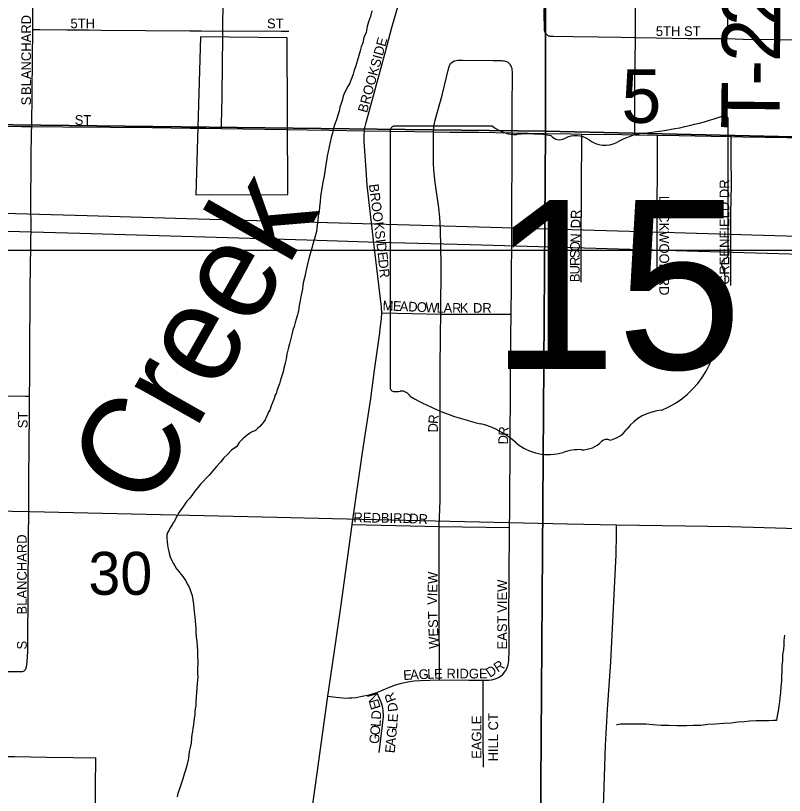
# Model space of a CAD drawing. Extents: x 0 to 68, y 0 to 52.9.
# Drawn here: x 44.415 to 45.206, y 36.702 to 37.505 of the extents above; entities that cross this region are included whole.
import ezdxf

# ---------------------------------------------------------------- set-up
doc = ezdxf.new("R2010")
doc.units = 0
for name, color, linetype in [('Default', 7, 'Continuous'), ('GM_X_County_Road', 7, 'Continuous'), ('GM_X_Minor_Lake', 7, 'Continuous'), ('GM_X_Minor_River', 7, 'Continuous'), ('GM_X_Minor_River_Text', 7, 'Continuous'), ('GM_X_State_Route', 7, 'Continuous'), ('GM_X_State_Shield', 7, 'Continuous'), ('GM_X_Township_Road', 7, 'Continuous'), ('GM_X_Township_Road_Text', 7, 'Continuous'), ('GM_X_Township_Subdivision', 7, 'Continuous'), ('GM_X_Township_Subdivision_Text', 7, 'Continuous')]:
    doc.layers.add(name, color=color, linetype=linetype)

msp = doc.modelspace()

# ---------------------------------------------------------------- linework, layer by layer
at = {"layer": 'Default'}
msp.add_line((41.10506, 37.2633), (50.34506, 37.2633), dxfattribs=at)
for points in [[(43.93627, 38.46518), (44.96064, 38.44451), (44.96032, 37.38586), (43.92065, 37.39833), (43.9204, 37.41034)], [(44.96064, 38.44451), (46.03674, 38.4191), (46.02513, 37.36139), (44.96032, 37.38586)], [(44.96032, 37.38586), (44.95281, 36.32851), (43.90273, 36.34073), (43.92065, 37.39833)], [(44.96032, 37.38586), (46.02513, 37.36139), (46.0139, 36.30128), (44.95281, 36.32851)]]:
    msp.add_lwpolyline(points, close=True, dxfattribs=at)
for points in [[(44.43227, 37.4907), (44.43277, 37.54226), (44.43273, 37.56524), (44.43292, 37.58162), (44.43311, 37.58761)], [(45.0529, 37.48225), (45.0529, 37.49022), (45.05337, 37.55402), (45.05339, 37.57852)], [(45.14747, 37.48118), (45.1476, 37.48856), (45.14788, 37.4984), (45.14842, 37.57791)], [(44.62788, 37.48889), (44.62836, 37.52296), (44.62854, 37.54361), (44.62857, 37.54875), (44.62898, 37.56606)], [(44.7737, 37.38631), (44.77418, 37.38918), (44.77571, 37.39488), (44.79524, 37.46651), (44.8022, 37.49277), (44.81318, 37.53091)], [(44.95931, 37.529), (44.9587, 37.50654), (44.95878, 37.49245), (44.95877, 37.49083), (44.95889, 37.48984), (44.95914, 37.48902), (44.95947, 37.48814), (44.95997, 37.48724), (44.96055, 37.4865), (44.96105, 37.48587), (44.96154, 37.48534), (44.96191, 37.48496), (44.96254, 37.48451), (44.96332, 37.48418), (44.96438, 37.48394), (44.96519, 37.48381), (44.96679, 37.48366), (44.96851, 37.48356), (44.98874, 37.48327), (45.01464, 37.48288), (45.03824, 37.48261), (45.0529, 37.48225)], [(44.43128, 37.39053), (44.43201, 37.46027), (44.43227, 37.4907)], [(44.43227, 37.4907), (44.43977, 37.49058), (44.46755, 37.49014), (44.48982, 37.49011), (44.50279, 37.49006), (44.59414, 37.48918), (44.60607, 37.48921), (44.62788, 37.48889)], [(44.62669, 37.38872), (44.62679, 37.39513), (44.62693, 37.40488), (44.62743, 37.42337), (44.62726, 37.42627), (44.62752, 37.43021), (44.62781, 37.44769), (44.62788, 37.48889)], [(44.62788, 37.48889), (44.67163, 37.48938), (44.68813, 37.4889), (44.69614, 37.48871)], [(45.05235, 37.38206), (45.05221, 37.43132), (45.0529, 37.48225)], [(45.0529, 37.48225), (45.07425, 37.48214), (45.10712, 37.48143), (45.14088, 37.48131), (45.14747, 37.48118)], [(45.14747, 37.48118), (45.16376, 37.48077), (45.19824, 37.48024), (45.21963, 37.47986), (45.22496, 37.47984)], [(44.84503, 37.38511), (44.84525, 37.38851), (44.84583, 37.39242), (44.84678, 37.39711), (44.85374, 37.42297), (44.86065, 37.45143), (44.86133, 37.45323), (44.86194, 37.45435), (44.86261, 37.45518), (44.86323, 37.4559)], [(44.92587, 37.38409), (44.92595, 37.41276), (44.92641, 37.4423), (44.92635, 37.44515), (44.92626, 37.44732), (44.92611, 37.44883), (44.92583, 37.45037), (44.9253, 37.45177), (44.92489, 37.45281), (44.92438, 37.45375), (44.924, 37.45447), (44.92337, 37.45522), (44.92255, 37.45604), (44.92195, 37.45647), (44.9214, 37.4569), (44.92042, 37.45741), (44.91933, 37.45774), (44.91825, 37.458), (44.91774, 37.45807), (44.91646, 37.45814), (44.91492, 37.45815), (44.90626, 37.45843), (44.87529, 37.45875), (44.86998, 37.45852), (44.86837, 37.45832), (44.86636, 37.45782), (44.86476, 37.45711), (44.86323, 37.4559)], [(44.37678, 37.39129), (44.42071, 37.39059), (44.43128, 37.39053)], [(44.42914, 37.11294), (44.42941, 37.13211), (44.42937, 37.15183), (44.42981, 37.22402), (44.43056, 37.28964), (44.43046, 37.30608), (44.43073, 37.35858), (44.43119, 37.3848), (44.43128, 37.39053)], [(44.43128, 37.39053), (44.46332, 37.39034), (44.51249, 37.38996), (44.55512, 37.38971), (44.59444, 37.38901), (44.61054, 37.389), (44.62669, 37.38872)], [(44.62669, 37.38872), (44.73757, 37.38674), (44.7737, 37.38631)], [(44.7737, 37.38631), (44.77331, 37.38154), (44.7734, 37.37522), (44.77516, 37.34613), (44.77639, 37.33038), (44.77923, 37.30625), (44.78351, 37.26792), (44.79105, 37.20461), (44.79154, 37.19887)], [(44.7737, 37.38631), (44.82588, 37.38538), (44.84503, 37.38511)], [(44.85258, 37.19723), (44.85294, 37.24938), (44.85234, 37.2841), (44.85155, 37.29719), (44.85049, 37.30696), (44.84676, 37.33293), (44.84537, 37.34596), (44.84507, 37.35251), (44.84482, 37.38104), (44.84503, 37.38511)], [(44.84503, 37.38511), (44.86194, 37.38488), (44.89145, 37.38473), (44.92587, 37.38409)], [(44.92484, 37.19732), (44.92535, 37.22609), (44.92557, 37.28191), (44.92587, 37.38409)], [(44.92587, 37.38409), (44.95892, 37.38351)], [(44.79154, 37.19887), (44.79099, 37.19255), (44.79055, 37.18753), (44.78988, 37.18239), (44.78923, 37.17816), (44.78373, 37.13976), (44.78009, 37.1106), (44.77156, 37.05483), (44.76097, 36.98081)], [(44.79154, 37.19887), (44.82273, 37.19803), (44.85258, 37.19723)], [(44.85091, 36.97849), (44.85177, 37.00572), (44.85179, 37.02867), (44.85179, 37.06146), (44.85196, 37.07129), (44.85169, 37.08437), (44.8517, 37.09749), (44.85199, 37.12694), (44.85189, 37.14005), (44.85215, 37.17611), (44.85258, 37.19723)], [(44.85258, 37.19723), (44.92484, 37.19732)], [(44.92315, 36.97752), (44.92349, 36.99448), (44.9238, 37.06997), (44.9241, 37.11591), (44.92444, 37.1747), (44.92484, 37.19732)], [(44.3738, 37.11383), (44.40167, 37.11332), (44.4246, 37.113), (44.42914, 37.11294)], [(44.4241, 36.83062), (44.42472, 36.83131), (44.4251, 36.83196), (44.42537, 36.83259), (44.42566, 36.8335), (44.42586, 36.83429), (44.42607, 36.83584), (44.42645, 36.83977), (44.42717, 36.84988), (44.42765, 36.91881), (44.42819, 37.00087), (44.42832, 37.02711), (44.42891, 37.09605), (44.42914, 37.11294)], [(44.76097, 36.98081), (44.75946, 36.97034), (44.74923, 36.89559), (44.74415, 36.85997), (44.74411, 36.85971)], [(44.76097, 36.98081), (44.82116, 36.97925), (44.85091, 36.97849)], [(44.85103, 36.82068), (44.85081, 36.89754), (44.85089, 36.9336), (44.85091, 36.97849)], [(44.85091, 36.97849), (44.92315, 36.97752)], [(44.92241, 36.84086), (44.92292, 36.85064), (44.92289, 36.86705), (44.92271, 36.88353), (44.92293, 36.92594), (44.92315, 36.97752)], [(44.89603, 36.82025), (44.89889, 36.82035), (44.90191, 36.82051), (44.90469, 36.82081), (44.90757, 36.82136), (44.91057, 36.82236), (44.91257, 36.82336), (44.91412, 36.82447), (44.91601, 36.82591), (44.91756, 36.82769), (44.91922, 36.82992), (44.92059, 36.83256), (44.92133, 36.83446), (44.92189, 36.83624), (44.92221, 36.83835), (44.92241, 36.84086)], [(44.37604, 36.83091), (44.37675, 36.83043), (44.37777, 36.83), (44.37863, 36.8298), (44.37961, 36.82971), (44.40172, 36.82944), (44.42085, 36.82929), (44.42186, 36.82939), (44.42268, 36.82964), (44.42348, 36.83011), (44.4241, 36.83062)], [(44.78672, 36.80784), (44.79954, 36.81331), (44.80577, 36.81551), (44.8121, 36.81733), (44.81855, 36.81872), (44.82508, 36.81964), (44.83166, 36.82014), (44.85103, 36.82068)], [(44.85103, 36.82068), (44.88121, 36.82049), (44.89603, 36.82025)], [(44.89645, 36.73063), (44.89625, 36.75774), (44.89624, 36.77412), (44.89603, 36.82025)], [(44.7359, 36.80397), (44.74477, 36.80298), (44.75177, 36.80232), (44.75498, 36.80198), (44.75777, 36.80202), (44.76087, 36.80221), (44.76486, 36.80266), (44.77152, 36.80377), (44.77862, 36.80532), (44.78672, 36.80784)], [(44.78897, 36.74588), (44.79254, 36.77387), (44.79344, 36.78289), (44.79346, 36.78496), (44.79329, 36.7874), (44.79312, 36.78933), (44.79278, 36.79144), (44.79235, 36.79318), (44.79127, 36.79661), (44.78982, 36.80076), (44.78672, 36.80784)], [(44.36531, 36.74204), (44.37442, 36.74185), (44.41389, 36.74175), (44.44674, 36.74103), (44.47406, 36.74072), (44.49737, 36.74023)], [(44.49339, 36.65802), (44.49427, 36.65935), (44.49475, 36.6604), (44.49515, 36.66144), (44.4955, 36.66231), (44.49584, 36.66328), (44.49606, 36.66402), (44.49617, 36.66453), (44.49628, 36.66538), (44.49632, 36.6661), (44.49645, 36.66784), (44.49658, 36.67009), (44.49675, 36.67664), (44.49691, 36.69163), (44.49708, 36.71008), (44.49737, 36.74023)]]:
    msp.add_lwpolyline(points, dxfattribs=at)
at = {"layer": 'GM_X_County_Road'}
for points in [[(44.95892, 37.38351), (44.9865, 37.38303), (44.99783, 37.38287)], [(44.99783, 37.38287), (45.03897, 37.38229), (45.05235, 37.38206)], [(45.05235, 37.38206), (45.07578, 37.38165)], [(45.07578, 37.38165), (45.09798, 37.38126), (45.13074, 37.38066), (45.15162, 37.38034)], [(45.15162, 37.38034), (45.16354, 37.38015), (45.20906, 37.37932), (45.22347, 37.37932)], [(43.68939, 37.00715), (43.6915, 37.00711), (43.7362, 37.00629), (44.09307, 37.00031), (44.42939, 36.99402), (44.68365, 36.98823), (44.74109, 36.98702), (44.98301, 36.98129), (45.03351, 36.98047)], [(45.03351, 36.98047), (45.15107, 36.97857), (45.32329, 36.97362), (45.4709, 36.96947), (45.6882, 36.96246), (45.69527, 36.96228), (45.70881, 36.96196)]]:
    msp.add_lwpolyline(points, dxfattribs=at)
at = {"layer": 'GM_X_Minor_Lake'}
for points in [[(44.69441, 37.48195), (44.60502, 37.48305), (44.60038, 37.32017)], [(44.69441, 37.48195), (44.60502, 37.48305), (44.60038, 37.32017), (44.69482, 37.32071), (44.69441, 37.48195)], [(44.60038, 37.32017), (44.69482, 37.32071), (44.69441, 37.48195)]]:
    msp.add_lwpolyline(points, dxfattribs=at)
at = {"layer": 'GM_X_Minor_River'}
for points in [[(44.78154, 37.50971), (44.78023, 37.50412), (44.77811, 37.49855), (44.7768, 37.49376), (44.77547, 37.48737), (44.77336, 37.48219), (44.77205, 37.477), (44.77036, 37.47263), (44.76947, 37.46863), (44.76817, 37.46384), (44.76687, 37.45905), (44.76559, 37.45547), (44.76473, 37.45228), (44.76345, 37.44869), (44.76217, 37.4447), (44.76088, 37.44072), (44.75835, 37.43475), (44.75628, 37.43158), (44.75543, 37.42919), (44.75334, 37.42522), (44.75208, 37.42204), (44.7512, 37.41845), (44.74991, 37.41446), (44.74863, 37.41047), (44.74775, 37.40648), (44.74646, 37.40249), (44.74516, 37.3977), (44.74347, 37.39333), (44.74216, 37.38854), (44.74086, 37.38375), (44.73957, 37.37936), (44.73867, 37.37456), (44.73737, 37.36978), (44.73647, 37.36498), (44.73557, 37.36018), (44.73467, 37.35539), (44.73419, 37.35138), (44.73329, 37.34659), (44.73234, 37.33939), (44.73101, 37.33339), (44.72871, 37.3186), (44.72819, 37.31299), (44.72769, 37.30778), (44.72719, 37.30298), (44.7263, 37.29858), (44.7258, 37.29378), (44.7253, 37.28898), (44.72436, 37.28257), (44.72263, 37.27619), (44.72091, 37.27061), (44.7196, 37.26542), (44.71788, 37.25943), (44.71615, 37.25345), (44.71482, 37.24746), (44.7135, 37.24147), (44.71259, 37.23627), (44.71128, 37.23108), (44.7104, 37.22709), (44.70992, 37.22309), (44.70859, 37.21709), (44.70767, 37.2115), (44.70677, 37.2063), (44.70586, 37.2011), (44.70497, 37.19671), (44.70367, 37.19232), (44.7024, 37.18873), (44.70151, 37.18474), (44.70023, 37.18075), (44.69893, 37.17636)], [(44.69893, 37.17636), (44.69805, 37.17237), (44.69673, 37.16678), (44.69542, 37.16159), (44.69411, 37.156), (44.69321, 37.1512), (44.69232, 37.14721), (44.69146, 37.14402), (44.69101, 37.14162), (44.69056, 37.13922), (44.6897, 37.13683), (44.68926, 37.13483), (44.68799, 37.13165), (44.68713, 37.12846), (44.68627, 37.12567), (44.68499, 37.12208), (44.68372, 37.11849), (44.68286, 37.1157), (44.68161, 37.11372), (44.68116, 37.11132), (44.67778, 37.10297), (44.67649, 37.09858), (44.67484, 37.09621), (44.67398, 37.09382), (44.67273, 37.09143), (44.67147, 37.08865), (44.66982, 37.08628), (44.66817, 37.0839), (44.66611, 37.08154), (44.66366, 37.07958), (44.66162, 37.07762), (44.65756, 37.07569), (44.65553, 37.07453), (44.65309, 37.07257), (44.65105, 37.07101), (44.6486, 37.06905), (44.64491, 37.06511), (44.64242, 37.06115), (44.63712, 37.05725), (44.63302, 37.05291), (44.62894, 37.04939), (44.62564, 37.04504), (44.62153, 37.04031), (44.61413, 37.03163), (44.61086, 37.02849), (44.60798, 37.02534), (44.60511, 37.02218), (44.60264, 37.01902), (44.59935, 37.01508), (44.59687, 37.01152), (44.59399, 37.00796), (44.59111, 37.00481), (44.58904, 37.00164), (44.58697, 36.99848), (44.58491, 36.99571), (44.58325, 36.99334), (44.58117, 36.98977), (44.57952, 36.98739), (44.57825, 36.98421), (44.57661, 36.98223), (44.57577, 36.98025), (44.57328, 36.97628), (44.57243, 36.9743), (44.57119, 36.97231), (44.57034, 36.96992), (44.57027, 36.96631), (44.57059, 36.9627), (44.57094, 36.95988), (44.57128, 36.95707), (44.57203, 36.95424), (44.57277, 36.95102), (44.5739, 36.94738), (44.57543, 36.94374), (44.57697, 36.9409), (44.57852, 36.93806), (44.58047, 36.93522), (44.58282, 36.93236), (44.58477, 36.92951), (44.58673, 36.92706), (44.58829, 36.92503), (44.58985, 36.92259), (44.5914, 36.91975), (44.59294, 36.91691), (44.5941, 36.91448), (44.59524, 36.91125), (44.59637, 36.90761), (44.59708, 36.90318), (44.59779, 36.89876), (44.5981, 36.89434), (44.59878, 36.88831), (44.59912, 36.88509), (44.59945, 36.88147), (44.59977, 36.87745), (44.6001, 36.87384), (44.60041, 36.86942), (44.60072, 36.865), (44.60142, 36.86017), (44.60173, 36.85535), (44.60202, 36.85013), (44.60192, 36.84491), (44.60222, 36.84009)], [(45.20638, 36.86674), (45.20586, 36.86123), (45.20585, 36.85721), (45.20534, 36.8517), (45.20433, 36.84668), (45.20431, 36.84066), (45.2038, 36.83465), (45.20378, 36.82963), (45.20327, 36.82461), (45.20326, 36.8196), (45.20274, 36.81358), (45.20223, 36.80756), (45.20171, 36.80205), (45.2012, 36.79803), (45.20069, 36.79402), (45.20018, 36.79101), (45.19866, 36.78149), (45.19815, 36.77898), (45.19514, 36.77899), (45.19012, 36.77851), (45.1841, 36.77853), (45.17708, 36.77855), (45.17055, 36.77807), (45.16503, 36.77758), (45.15851, 36.7771), (45.15148, 36.77612), (45.14396, 36.77564), (45.13493, 36.77517), (45.1274, 36.77469), (45.12038, 36.77371), (45.11285, 36.77373), (45.10532, 36.77326)], [(44.60222, 36.84009), (44.60216, 36.83688), (44.60208, 36.83327), (44.60202, 36.83007), (44.60195, 36.82686), (44.6023, 36.82404), (44.60182, 36.82044), (44.60175, 36.81683), (44.60125, 36.81203), (44.60017, 36.79841), (44.60008, 36.79399), (44.59962, 36.7908), (44.59916, 36.788), (44.59909, 36.78479), (44.59862, 36.78119), (44.59815, 36.77799), (44.59768, 36.77438), (44.5972, 36.77078), (44.59674, 36.76758), (44.59627, 36.76438), (44.5958, 36.76078), (44.59529, 36.75558), (44.5944, 36.75118), (44.59351, 36.74679), (44.59303, 36.74318), (44.59257, 36.73998), (44.5921, 36.73678), (44.59081, 36.7324), (44.58951, 36.72761), (44.58822, 36.72362), (44.58692, 36.71883), (44.58521, 36.71365), (44.5835, 36.70847), (44.5818, 36.70369), (44.58092, 36.7001)], [(45.10532, 36.77326), (45.09629, 36.77329), (45.08776, 36.77382), (45.07924, 36.77384), (45.07071, 36.77437), (45.06368, 36.77489), (45.05616, 36.77492), (45.04713, 36.77495), (45.04161, 36.77496), (45.0376, 36.77498), (45.03408, 36.77449), (45.03408, 36.77449), (45.03358, 36.77449)]]:
    msp.add_lwpolyline(points, dxfattribs=at)
at = {"layer": 'GM_X_State_Route'}
for points in [[(43.67519, 37.30421), (43.6819, 37.30396), (43.8786, 37.29812), (44.06297, 37.29264), (44.2064, 37.28832), (44.48097, 37.28067), (44.71457, 37.27378), (44.78831, 37.27138), (44.88259, 37.269), (45.2473, 37.25834), (45.44401, 37.2525), (45.57514, 37.24871), (45.72414, 37.24408), (45.83581, 37.24067)], [(44.4022, 37.30142), (44.48825, 37.29907), (44.59065, 37.29602), (44.82018, 37.28924), (45.07034, 37.28217), (45.17284, 37.27923), (45.30366, 37.2754), (45.39409, 37.27235), (45.48453, 37.27009), (45.65226, 37.26547), (45.72506, 37.2633), (45.89, 37.25838)]]:
    msp.add_lwpolyline(points, dxfattribs=at)
at = {"layer": 'GM_X_State_Shield'}
for p, q in [((44.9058, 37.39093), (44.80388, 37.39093)), ((45.14849, 37.25929), (45.14849, 37.39747)), ((44.80045, 37.38638), (44.80045, 37.12222)), ((45.14846, 37.25932), (45.14849, 37.25929))]:
    msp.add_line(p, q, dxfattribs=at)
for centre, radius, start, end in [((45.02451, 37.75107), 0.36909, 275.84447, 288.90645), ((45.14463, 37.39805), 0.00387, 351.86209, 97.738), ((44.80444, 37.38695), 0.00403, 98.1301, 188.1301), ((44.93008, 37.42159), 0.03911, 231.61951, 271.11188), ((44.94304, 37.24263), 0.1404, 80.48669, 94.98827), ((45.07159, 37.31025), 0.07426, 97.34618, 120.76885), ((44.97492, 37.38831), 0.01128, 219.79206, 297.10237), ((44.99148, 37.35778), 0.02346, 54.46668, 119.14113), ((45.02176, 37.39966), 0.02822, 233.85621, 294.82819), ((45.1476, 37.24914), 0.006, 107.94398, 210.33697), ((45.14436, 37.25876), 0.00415, 289.60381, 7.73413), ((45.10945, 37.23168), 0.03599, 340.03296, 23.64957), ((45.16237, 37.20146), 0.02619, 136.8065, 186.92959), ((45.04519, 37.18388), 0.09232, 292.30889, 8.98584), ((44.80447, 37.12165), 0.00407, 171.95839, 258.30661), ((44.80509, 37.14867), 0.03104, 267.33899, 280.60386), ((44.81144, 37.10698), 0.01119, 29.74838, 93.27175), ((44.95276, 37.34432), 0.26654, 240.41292, 257.1985), ((45.08412, 37.04806), 0.05056, 94.40312, 142.57675), ((44.8733, 37.00355), 0.08339, 47.18416, 75.83597), ((45.02006, 37.09662), 0.02983, 282.87319, 323.27711), ((44.96349, 37.10567), 0.05292, 230.70037, 286.29184), ((44.99794, 37.08589), 0.0282, 268.77702, 315.54927), ((45.02344, 37.06031), 0.00794, 65.75173, 132.64842), ((44.99407, 37.01434), 0.04348, 85.69512, 111.20995)]:
    msp.add_arc(centre, radius, start, end, dxfattribs=at)
at = {"layer": 'GM_X_Township_Road'}
for points in [[(45.008, 35.98469), (45.01067, 36.14211), (45.01366, 36.3513), (45.01446, 36.41283), (45.01571, 36.48666), (45.01707, 36.59742), (45.01813, 36.63842), (45.02022, 36.69992), (45.02207, 36.75323), (45.02424, 36.79008), (45.02762, 36.83919), (45.03292, 36.94983), (45.03331, 36.97034), (45.03351, 36.98047)], [(44.74411, 36.85971), (44.7359, 36.80397)], [(44.7359, 36.80397), (44.73378, 36.78902), (44.72799, 36.74677), (44.71954, 36.68755)]]:
    msp.add_lwpolyline(points, dxfattribs=at)
at = {"layer": 'GM_X_Township_Subdivision'}
for points in [[(44.99719, 37.26841), (44.99783, 37.38287)], [(45.0754, 37.27468), (45.07578, 37.38165)], [(45.15125, 37.26932), (45.15122, 37.30129), (45.15169, 37.32983), (45.15157, 37.35996), (45.15161, 37.37316), (45.15162, 37.38034)], [(45.07524, 37.22809), (45.0754, 37.27468)], [(44.99698, 37.23026), (44.99719, 37.26841)], [(45.151, 37.22703), (45.15125, 37.26818), (45.15125, 37.26932)]]:
    msp.add_lwpolyline(points, dxfattribs=at)

# ---------------------------------------------------------------- texts
at = {"layer": 'Default'}
for s, height, rotation, p in [('BLANCHARD', 0.01, 90, (44.43054, 37.42306)), ('5TH', 0.01, 0.00001, (44.47114, 37.49182)), ('ST', 0.01, 0.00001, (44.67353, 37.49182)), ('5TH ST', 0.01, 0.00001, (45.07394, 37.4839)), ('BROOKSIDE', 0.01, 74.55378, (44.77644, 37.4042)), ('5', 0.05525, 0.00001, (45.0385, 37.3944)), ('S', 0.01, 90, (44.43054, 37.4125)), ('ST', 0.01, 0.00001, (44.47554, 37.39238)), ('BROOKSIDE', 0.01, 277.30463, (44.77836, 37.3309)), ('DR', 0.01, 276.0168, (44.78804, 37.25342)), ('M', 0.01, 357.48592, (44.79241, 37.20142)), ('E', 0.01, 357.49083, (44.80297, 37.20096)), ('A', 0.01, 357.48576, (44.81, 37.20065)), ('D', 0.01, 357.49331, (44.81879, 37.20026)), ('O', 0.01, 357.48576, (44.82758, 37.19988)), ('W', 0.01, 357.47759, (44.83637, 37.19949)), ('L', 0.01, 358.58833, (44.84802, 37.19898)), ('A', 0.01, 359.89125, (44.8553, 37.1988)), ('R', 0.01, 359.99406, (44.86413, 37.19878)), ('K', 0.01, 359.99285, (44.87205, 37.19878)), ('DR', 0.01, 0.00001, (44.88562, 37.19878)), ('ST', 0.01, 90, (44.42701, 37.07986)), ('R', 0.01, 85.42994, (44.84955, 37.08405)), ('D', 0.01, 89.08194, (44.84942, 37.07542)), ('R', 0.01, 85.47835, (44.9218, 37.07173)), ('D', 0.01, 88.49198, (44.92158, 37.06307)), ('REDBIRD', 0.01, 359.0577, (44.76245, 36.98306)), ('DR', 0.01, 356.98902, (44.81971, 36.98217)), ('BLANCHARD', 0.01, 90, (44.42613, 36.88802)), ('30', 0.0442, 0.00001, (44.48962, 36.90832)), ('VIEW', 0.01, 88.45263, (44.84854, 36.89775)), ('VIEW', 0.01, 90, (44.9207, 36.88978)), ('WEST', 0.01, 91.50669, (44.85029, 36.85277)), ('EAST', 0.01, 90, (44.92069, 36.85194)), ('S', 0.01, 90, (44.42613, 36.85194)), ('DR', 0.01, 33.69679, (44.90305, 36.8227)), ('E', 0.01, 4.65018, (44.81417, 36.82037)), ('A', 0.01, 2.99556, (44.82111, 36.82094)), ('G', 0.01, 1.74895, (44.82984, 36.8214)), ('L', 0.01, 1.66701, (44.83863, 36.82167)), ('E', 0.01, 1.68905, (44.84568, 36.82187)), ('RIDGE', 0.01, 0.00001, (44.85833, 36.82214)), ('N', 0.01, 105.75927, (44.7886, 36.79862)), ('R', 0.01, 110.84081, (44.80667, 36.79973)), ('E', 0.01, 107.09753, (44.79065, 36.79196)), ('D', 0.01, 97.19916, (44.8084, 36.78848)), ('D', 0.01, 88.67533, (44.79093, 36.77969)), ('E', 0.01, 86.53133, (44.80792, 36.77679)), ('EAGLE', 0.01, 90, (44.89429, 36.7393)), ('HILL CT', 0.01, 90, (44.9115, 36.73666)), ('O', 0.01, 84.90228, (44.78948, 36.7632)), ('L', 0.01, 84.90969, (44.79026, 36.77196)), ('L', 0.01, 84.93437, (44.80728, 36.76947)), ('G', 0.01, 84.90055, (44.7887, 36.75443)), ('G', 0.01, 84.60876, (44.80645, 36.76065)), ('A', 0.01, 84.56381, (44.80561, 36.75188)), ('E', 0.01, 84.55577, (44.80494, 36.74487))]:
    msp.add_text(s, height=height, rotation=rotation, dxfattribs=at).set_placement(p)
at = {"layer": 'GM_X_Minor_River_Text'}
msp.add_text('Creek', height=0.100043, rotation=60.46201, dxfattribs=at).set_placement((44.55199, 36.99315))
at = {"layer": 'GM_X_State_Shield'}
msp.add_text('15', height=0.174024, dxfattribs=at).set_placement((44.90408, 37.14085))
at = {"layer": 'GM_X_Township_Road_Text'}
for s, rotation, p in [('2', 89.51026, (45.20207, 37.49364)), ('2', 89.57487, (45.20179, 37.45699)), ('-', 89.46716, (45.20157, 37.43245)), ('T', 89.43115, (45.20112, 37.38762))]:
    msp.add_text(s, height=0.06, rotation=rotation, dxfattribs=at).set_placement(p)
at = {"layer": 'GM_X_Township_Subdivision_Text'}
for s, rotation, p in [('GREENFIELD DR', 90, (45.14949, 37.2277)), ('LOCKWOOD RD', 270, (45.07758, 37.31922)), ('DR', 90, (44.99637, 37.28578)), ('N', 86.21645, (44.9957, 37.27064)), ('O', 88.68861, (44.99551, 37.26196)), ('S', 89.94534, (44.9955, 37.25498)), ('R', 89.97031, (44.9955, 37.24706)), ('U', 89.95627, (44.99549, 37.23826)), ('B', 89.9757, (44.99549, 37.23034))]:
    msp.add_text(s, height=0.01, rotation=rotation, dxfattribs=at).set_placement(p)

doc.saveas('drawing.dxf')
